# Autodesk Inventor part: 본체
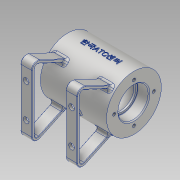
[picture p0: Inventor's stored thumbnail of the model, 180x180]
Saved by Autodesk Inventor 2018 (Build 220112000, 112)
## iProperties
Created: 2021-12
Part Number: 본체
Material: 알루미늄 6061
Document SubType Name: Modeling
Designer: home
Density: 2.7 g/cm^3
Appearance: 알루미늄 - 평지
Mass: 309.904 g
Surface Area: 352.479 cm^2
Volume: 114.779 cm^3
Author: home
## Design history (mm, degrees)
sketch "스케치1"
  geometry: L1 (-35, 0)-(35, 0); L2 (-35, 0)-(-35, 29); L3 (-35, 29)-(35, 29); L4 (35, 29)-(35, 0); L5 (-35, 16)-(-23.3, 16); L6 (-23, 15.7)-(-23, 14); L7 (-23, 14)-(-21, 14); L8 (-21, 14)-(-21, 18); L9 (-18, 21)-(18, 21); L10 (21, 18)-(21, 14); L11 (21, 14)-(23, 14); L12 (23, 14)-(23, 15.7); L13 (23.3, 16)-(35, 16); A1 r 0.3 centre (-23.3, 15.7) between (-23, 15.7) and (-23.3, 16); A2 r 0.3 centre (23.3, 15.7) between (23.3, 16) and (23, 15.7); A3 r 3 centre (-18, 18) between (-18, 21) and (-21, 18); A4 r 3 centre (18, 18) between (21, 18) and (18, 21); 6 further points
  constraints: 26 end point, 14 point on line, 8 point on circle, 8 tangent, 7 perpendicular, 4 centre point, 3 horizontal, 2 equal radius, 2 midpoint, 1 vertical
  dimensions: "d0" = 70 distance of L1.start L1.end; "d1" = 35 distance of L1.start point (0, 0); "d2" = 58 diameter of L3 L1; "d3" = 42 diameter of L9 L1; "d4" = 32 diameter of L5 L1; "d5" = 28 diameter of L7 L1; "d6" = 12 distance of L5.start point (-23, 16); "d7" = 42 distance of point (-21, 21) point (21, 21); "d8" = 12 distance of point (23, 16) L13.end; "d9" = 2 distance of L6.end L7.end; "d11" = 0.3 radius of A1; "d12" = 3 radius of A3
revolve "회전1" sketch "스케치1" stored, may be unused: angle "d10" = 90 deg
node "작업 평면1"
sketch "스케치2"
  geometry: C1 r 5 at (0, 0); 1 further point
  constraints: 1 centre point, 1 coincident
  dimensions: "d14" = 10 diameter of C1
extrude "돌출1" join sketch "스케치2" stored distance "d15" = 10; taper "d16" = 0 deg
node "작업 평면2"
sketch "스케치3"
  geometry: L1 (-55, -30.582)-(-55, 30.582); L2 (-17.993, -22.743)-(-46.464, -36.02); L3 (-46.464, 36.02)-(-17.993, 22.743); A1 r 29 centre (0, 0) between (-17.993, -22.743) and (-17.993, 22.743) reference; A2 r 6 centre (-49, -30.582) between (-55, -30.582) and (-46.464, -36.02); A3 r 6 centre (-49, 30.582) between (-46.464, 36.02) and (-55, 30.582); 3 further points
  constraints: 6 end point, 6 point on circle, 4 point on line, 4 tangent, 2 centre point, 1 equal radius, 1 vertical
  dimensions: "d18" = 80 distance of point (-55, -40) point (-55, 40); "d19" = 40 vertical distance of point (-55, -40) point (0, 0); "d20" = 65 deg angle of L1 L2; "d21" = 65 deg angle of L1 L3; "d22" = 55 distance from line of L1 point (0, 0); "d23" = 6 radius of A2
extrude "돌출2" join sketch "스케치3" distance "d24" = 12; taper "d25" = 0 deg
sketch "스케치4"
  geometry: L1 (-36.02, -46.464)-(-22.743, -17.993) reference; L2 (30.582, -55)-(-30.582, -55) reference; L3 (22.743, -17.993)-(36.02, -46.464) reference; L4 (-20.574, -20.438)-(-33.301, -47.732); L5 (-30.582, -52)-(30.582, -52); L6 (33.301, -47.732)-(20.574, -20.438); A1 r 6 centre (-30.582, -49) between (-36.02, -46.464) and (-30.582, -55) reference; A2 r 6 centre (30.582, -49) between (30.582, -55) and (36.02, -46.464) reference; A3 r 29 centre (0, 0) between (20.574, -20.438) and (-20.574, -20.438); A4 r 3 centre (-30.582, -49) between (-33.301, -47.732) and (-30.582, -52); A5 r 3 centre (30.582, -49) between (30.582, -52) and (33.301, -47.732); 1 further point
  constraints: 6 end point, 6 point on circle, 3 centre point, 1 coincident, 2 other
  dimensions: "d26" = 58 diameter of A3; "d27" = 3 distance between parallel lines of L1 L4; "d28" = 3 distance between parallel lines of L3 L6; "d29" = 3 distance between parallel lines of L2 L5
extrude "돌출3" cut sketch "스케치4" distance "d30" = 12; taper "d31" = 0 deg
sketch "스케치5" dims "d32" = 42
  geometry: 3 further points
  constraints: 1 coincident, 1 vertical alignment, 2 other
hole "구멍1" sketch "스케치5" at (0, 21) diameter "d33" = 3.242; stored, may be unused: countersink angle "d37" = 90 deg, drill point angle "d39" = 118 deg; dims "d34" = 8, "d35" = 4, "d36" = 2, "d38" = 10
sketch "스케치6"
  geometry: 2 further points
  constraints: 1 coincident
hole "구멍2" sketch "스케치6" at (0, 0) diameter "d43" = 5.188; stored, may be unused: countersink angle "d47" = 90 deg, drill point angle "d49" = 118 deg; dims "d44" = 6, "d45" = 4, "d46" = 2, "d48" = 8
sketch "스케치7"
  geometry: C1 r 2.594 at (0, 0) reference; 2 further points
  constraints: 1 coincident
hole "구멍3" sketch "스케치7" at (0, 0) diameter "d50" = 3; stored, may be unused: countersink angle "d54" = 90 deg, drill point angle "d56" = 0 deg; dims "d51" = 6, "d52" = 4, "d53" = 2, "d55" = 30
sketch "스케치8"
  geometry: L1 (6, 48.582)-(54, 48.582); L2 (54, 48.582)-(54, 12.582); L3 (54, 12.582)-(6, 12.582); L4 (6, 12.582)-(6, 48.582); L5 (6, 48.582)-(54, 12.582); L6 (54, 48.582)-(6, 12.582); C1 r 2.594 at (30, 30.582) reference; C2 r 3 at (6, 48.582); C3 r 3 at (6, 12.582); C4 r 3 at (54, 12.582); C5 r 3 at (54, 48.582); 1 further point
  constraints: 12 end point, 4 centre point, 4 coincident, 2 midpoint, 2 parallel, 1 horizontal, 1 perpendicular
  dimensions: "d57" = 48 distance of L2.end L3.end; "d58" = 36 distance of L1.end L2.end; "d59" = 6 diameter of C2; "d60" = 6 diameter of C3; "d61" = 6 diameter of C4; "d62" = 6 diameter of C5
extrude "돌출4" cut sketch "스케치8" distance "d63" = 5; taper "d64" = 0 deg
fillet "모깎기1" dims "d65" = 1
fillet "모깎기2" dims "d66" = 0.5
fillet "모깎기3" dims "d67" = 3
chamfer "모따기1" distance "d68" = 1; stored, may be unused: second distance "d69" = 2, angle "d70" = 45 deg
node "작업 평면4"
sketch "스케치9"
  geometry: L1 (-35, -29)-(-35, 29) reference; L2 (-35, 29)-(35, 29) reference; 2 further points
  constraints: 1 other
  dimensions: "d72" = 35 distance from line of L1 point (0, 0.353); "d73" = 29 distance from line of point (0, 0) L2 (derived)
feature "엠보싱1" sketch "스케치9" dims "d74" = 0.5, "d75" = 0
sketch "스케치10"
  geometry: L1 (0, 0)-(-30.07, -10.945); L2 (0, 0)-(-37, 0)
  constraints: 4 end point, 1 horizontal
  dimensions: "d76" = 20 deg angle of L2 L1; "d77" = 32 distance of L1.start L1.end
node "작업 평면5"
sketch "스케치11"
  geometry: C1 r 6 at (0, 0); 1 further point
  constraints: 1 centre point, 1 coincident
  dimensions: "d79" = 12 diameter of C1
extrude "돌출5" join sketch "스케치11" stored distance "d80" = 0; taper "d81" = 0 deg
sketch "스케치12"
  geometry: 2 further points
  constraints: 1 coincident
hole "구멍4" sketch "스케치12" at (0, 0) diameter "d82" = 5.188; stored, may be unused: countersink angle "d86" = 90 deg, drill point angle "d88" = 0 deg; dims "d83" = 30, "d84" = 4, "d85" = 2, "d87" = 30
fillet "모깎기4" dims "d89" = 1
node "솔리드1"
mirror "미러1"
pattern_circular "원형 패턴1" dims angle "d41" = 360 deg
mirror "미러2"
node "작업 평면3"
other parameters: "d13" = 32, "d71" = 29
